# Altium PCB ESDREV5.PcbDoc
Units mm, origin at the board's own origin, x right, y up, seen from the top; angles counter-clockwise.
Board outline 53.34 x 50.29 mm, 2 copper layers (TopLayer, BottomLayer); 24 components, 34 nets, 104 pads, 29 vias.
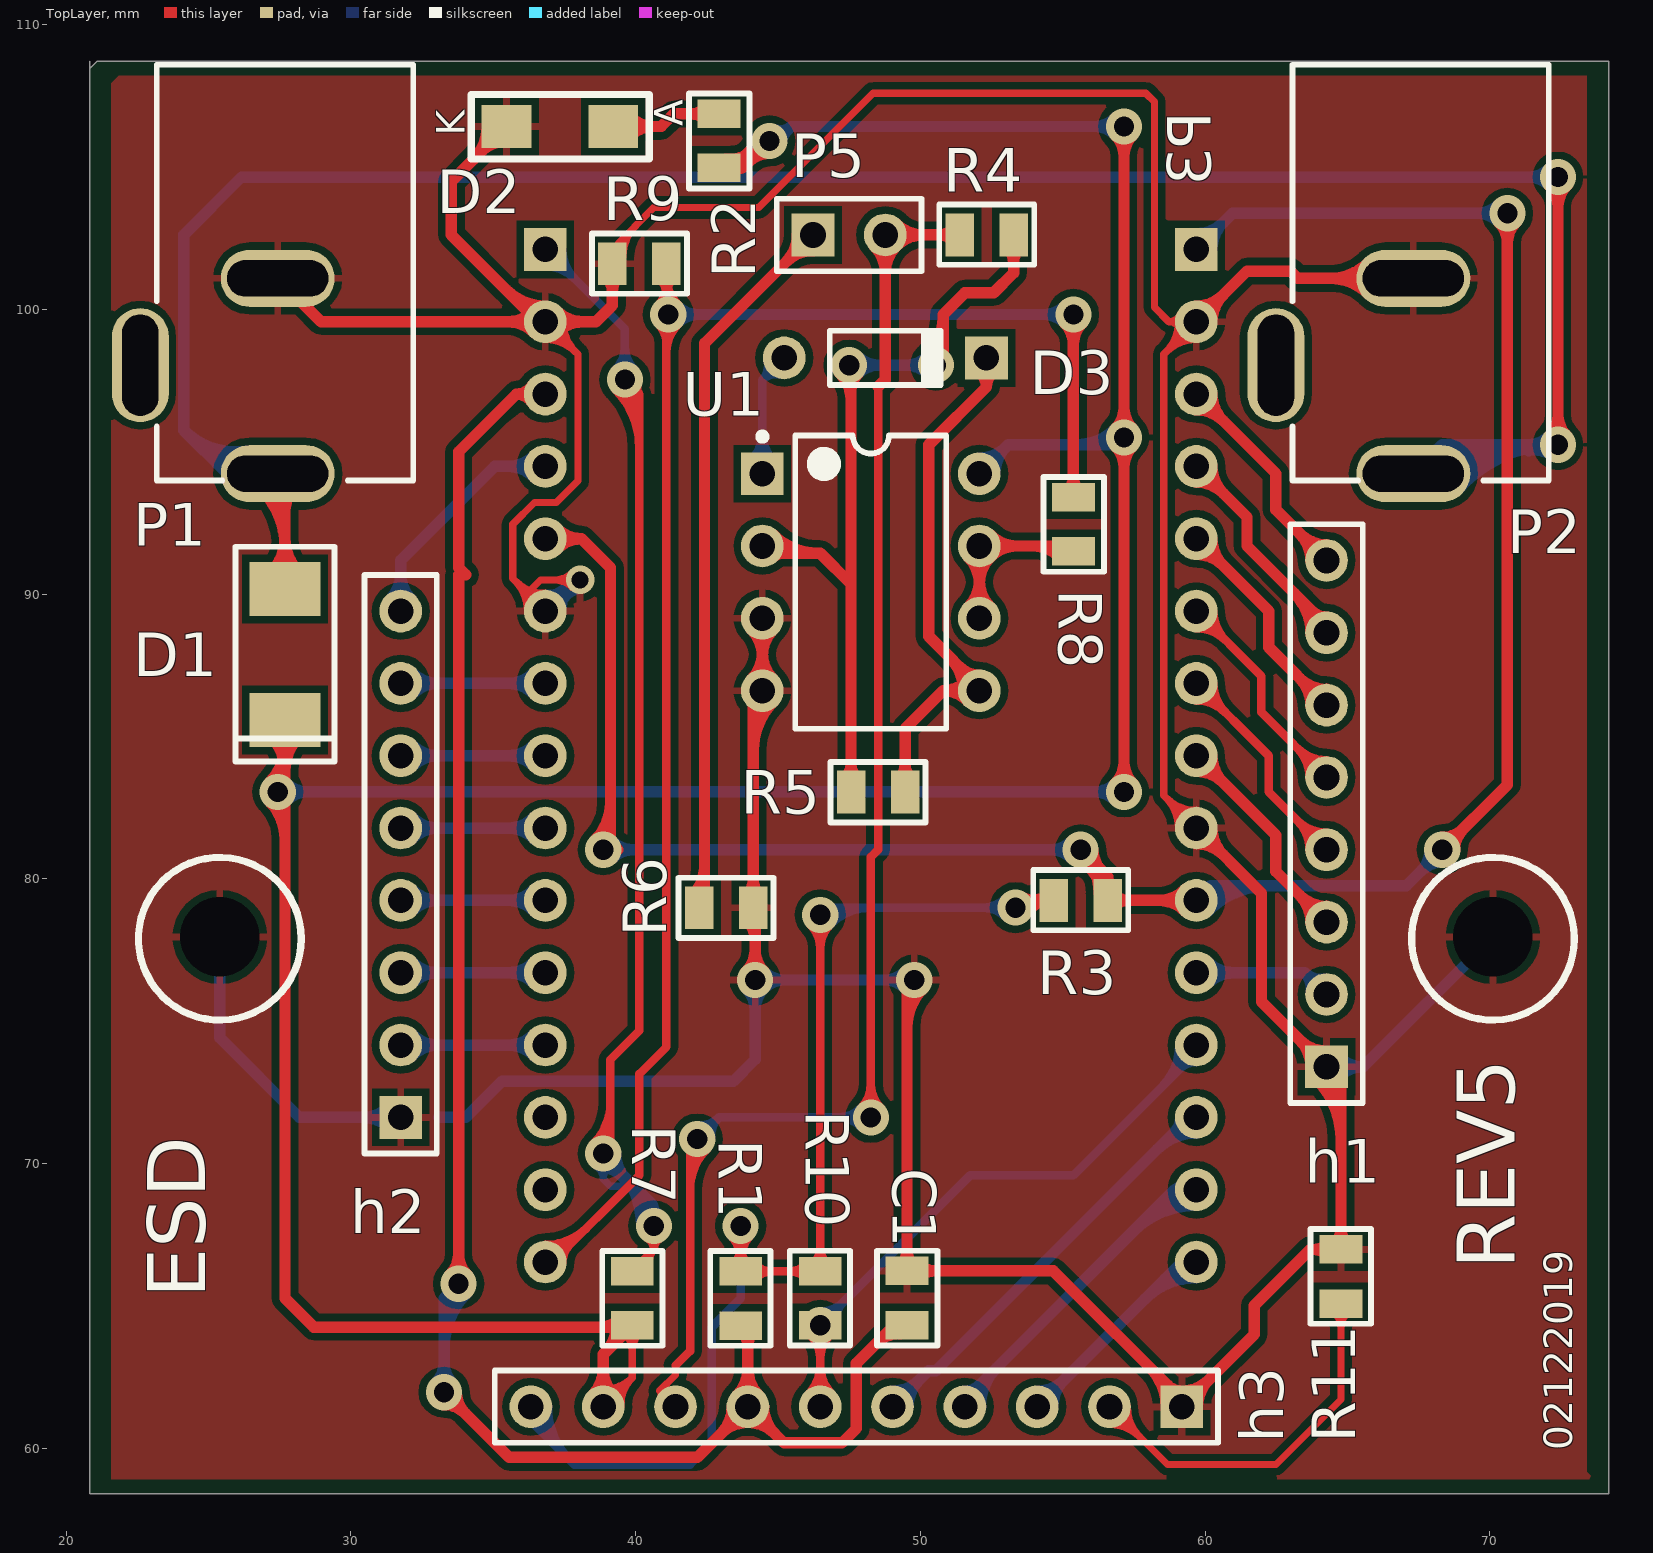
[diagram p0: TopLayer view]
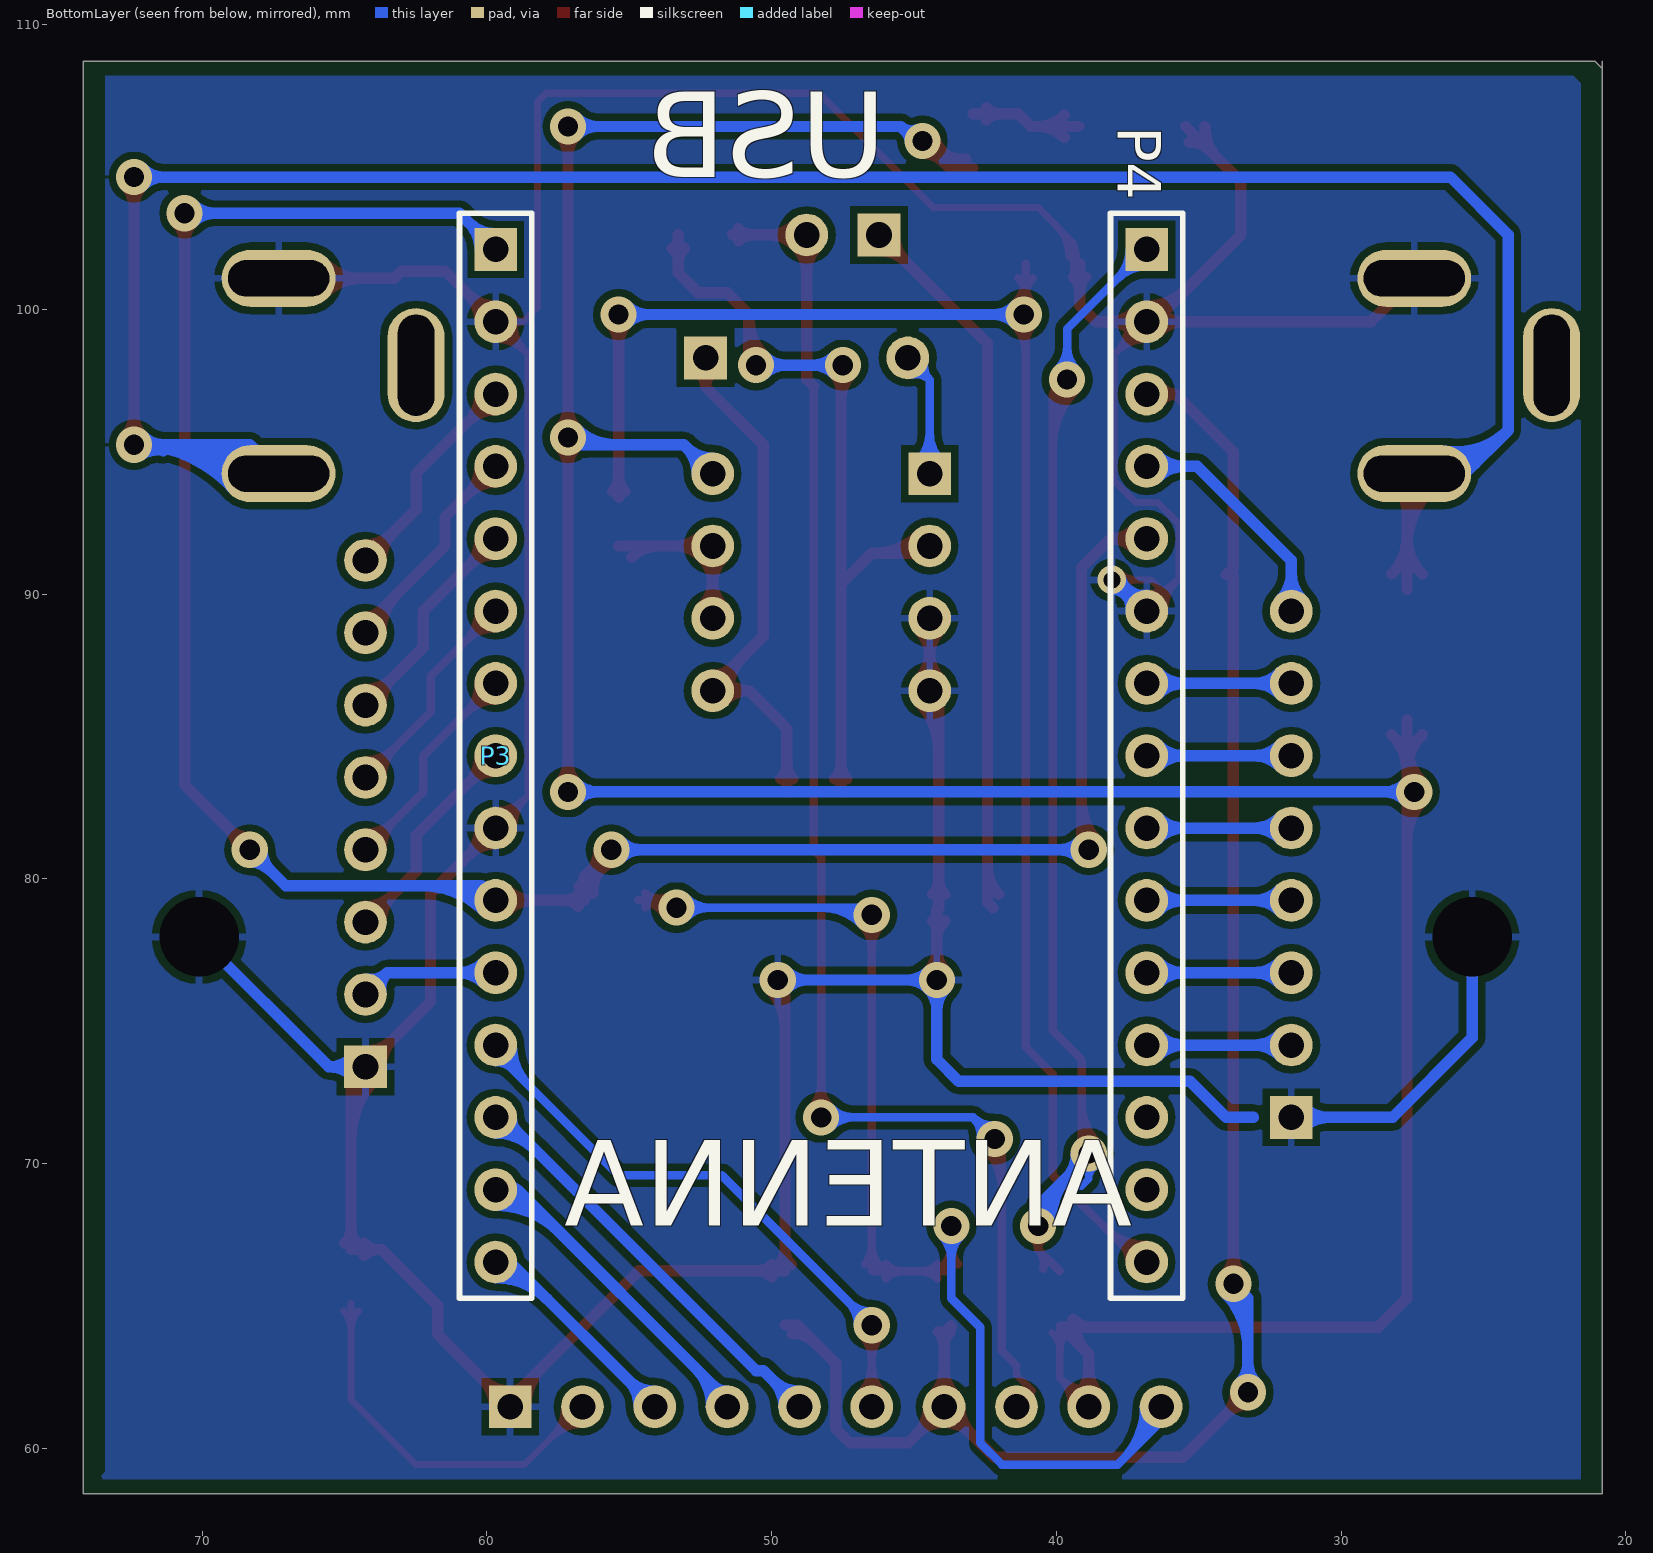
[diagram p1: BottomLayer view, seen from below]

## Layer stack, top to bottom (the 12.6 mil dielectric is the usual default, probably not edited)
TopLayer: signal copper 0.0356
Dielectric: core 0.32, FR-4, Dk 4.8
BottomLayer: signal copper 0.0356

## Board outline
20.828,108.458 21.082,108.712 74.168,108.712 74.168,58.42 20.828,58.42 20.828,108.712

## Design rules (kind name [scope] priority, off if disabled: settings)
AssemblyTestPointUsage AssemblyTestPointUsage_1 [All] p2:
AssemblyTestpoint AssemblyTestpoint_1 [All] p2: testpointundercomponent=TRUE minsize=1.016 maxsize=2.54 preferedsize=1.524 minholesize=0 maxholesize=1.016 preferedholesize=0.813 testpointgrid=0.025 usegrid=TRUE gridtolerance=0 allowsidetop=TRUE allowsidebottom=TRUE
Clearance [All] p1: gap=0.254
ComponentClearance ComponentClearance_1 [All] p2: gap=0.254 collisioncheckmode=3 verticalgap=0.254 showdistances=FALSE
DiffPairsRouting DiffPairsRouting_1 [All] p2: maxlimit=0.254 minlimit=0.254 mostfreqgap=0.254 maxuncoupledlength=12.7
FabricationTestPointUsage TestPointUsage [All] p2: valid=0 allowmultiple=FALSE
FabricationTestpoint Testpoint [All] p2: side=3 testpointundercomponent=TRUE minsize=1.016 maxsize=2.54 preferedsize=1.524 minholesize=0.508 maxholesize=1.016 preferedholesize=0.813 testpointgrid=0.025 allowsidetop=TRUE allowsidebottom=TRUE usegrid=TRUE gridtolerance=0
FanoutControl Fanout_LCC [IsLCC] p1: bgadir=Out bgaviamode=Centered fanoutstyle=Auto fanoutdirection=Alternating viagrid=0.025 // Fanout_LCC (Default Rule)
FanoutControl Fanout_BGA [IsBGA] p2: bgadir=Out bgaviamode=Centered fanoutstyle=Auto fanoutdirection=Alternating viagrid=0.025 // Fanout_BGA (Default Rule)
FanoutControl Fanout_Small [(CompPinCount < 5)] p3: bgadir=Out bgaviamode=Centered fanoutstyle=Auto fanoutdirection=OutThenIn viagrid=0.025 // Fanout_Small (Default Rule)
FanoutControl Fanout_SOIC [IsSOIC] p4: bgadir=Out bgaviamode=Centered fanoutstyle=Auto fanoutdirection=Alternating viagrid=0.025 // Fanout_SOIC (Default Rule)
FanoutControl Fanout_BGA_1 [IsBGA] p6: bgadir=Out bgaviamode=Centered fanoutstyle=Auto fanoutdirection=Alternating viagrid=0.025 // Fanout_BGA (Default Rule)
FanoutControl Fanout_LCC_1 [IsLCC] p7: bgadir=Out bgaviamode=Centered fanoutstyle=Auto fanoutdirection=Alternating viagrid=0.025 // Fanout_LCC (Default Rule)
FanoutControl Fanout_SOIC_1 [IsSOIC] p8: bgadir=Out bgaviamode=Centered fanoutstyle=Auto fanoutdirection=Alternating viagrid=0.025 // Fanout_SOIC (Default Rule)
FanoutControl Fanout_Small_1 [(CompPinCount < 5)] p9: bgadir=Out bgaviamode=Centered fanoutstyle=Auto fanoutdirection=OutThenIn viagrid=0.025 // Fanout_Small (Default Rule)
FanoutControl Fanout_Default_1 [All] p10: bgadir=Out bgaviamode=Centered fanoutstyle=Auto fanoutdirection=Alternating viagrid=0.025 // Fanout_Default (Default Rule)
Height Height_1 [All] p2: minheight=0 maxheight=25.4 prefheight=12.7
HoleSize HoleSize_1 [All] p2: absolutevalues=TRUE maxlimit=2.54 minlimit=0.025 maxpercent=80.000 minpercent=20.000
HoleToHoleClearance HoleToHoleClearance_1 [All] p2: gap=0.254 allowstackedmicrovias=TRUE
LayerPairs LayerPairs_1 [All] p2: enforce=TRUE
MinimumSolderMaskSliver MinimumSolderMaskSliver_1 [All] p2: minsoldermaskwidth=0.254
NetAntennae NetAntennae_1 [All] p2: netantennaetolerance=0
PasteMaskExpansion PasteMaskExpansion_1 [All] p2: expansion=0
PlaneClearance PlaneClearance_1 [All] p2: clearance=0.254
PolygonConnect [All] p1: connectstyle=Relief reliefconductorwidth=0.254 reliefentries=4 polygonreliefangle="90 Angle" airgapwidth=0.254
PolygonConnect PolygonConnect_1 [All] p2: connectstyle=Relief reliefconductorwidth=0.254 reliefentries=4 polygonreliefangle="90 Angle" airgapwidth=0.254
RoutingPriority RoutingPriority_1 [All] p2: routingpriority=0
RoutingTopology RoutingTopology_1 [All] p2: topology=Shortest
RoutingVias [All] p1: holewidth=0.6 width=1 viastyle="Through Hole" minholewidth=0.711 minwidth=1.27 maxholewidth=0.711 maxwidth=1.27
ShortCircuit ShortCircuit_1 [All] p2: allowed=FALSE
SilkToSilkClearance SilkToSilkClearance_1 [All] p2: silktosilkclearance=0.254
SilkToSolderMaskClearance SilkscreenOverComponentPads [IsPad] p2: minsilkscreentomaskgap=0.254 clearancetoexposedcopper=TRUE
SolderMaskExpansion [All] p1: expansion=0.102
SolderMaskExpansion SolderMaskExpansion_1 [All] p2: expansion=0.051
UnRoutedNet UnRoutedNet_1 [All] p2:
Width [All] p1: maxlimit=0.5 minlimit=0.254 preferedwidth=0.254
24 further rules are at their usual default settings.

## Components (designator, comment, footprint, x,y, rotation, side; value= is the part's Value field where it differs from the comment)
C1 "100nF" 0805#1 49.53,65.278 r270 top
D1 "1.5A, PIV 1KV" DO-214AA 27.686,87.884 r90 top
D2 "LED3" "0537, LED, 1206" 37.338,106.426 r0 top
D3 "Diode 1N4448" DO-35 48.768,98.298 r0 top
h1 "Header 8" HDR1X8 64.262,73.406 r90 top
h2 "Header 8" HDR1X8 31.75,71.628 r90 top
h3 "Header 10" HDR1X10 59.182,61.468 r180 top
P1 "Header 2" DCJACK 27.432,101.092 r270 top
P2 "Header 2" DCJACK 67.31,101.092 r270 top
P3 "Header 15" HDR1X15 59.69,102.108 r270 bottom
P4 "Header 15" HDR1X15 36.83,102.108 r270 bottom
P5 "Header 2" HDR1X2 46.228,102.616 r0 top
R1 "" 0805#1 43.688,65.278 r90 top
R2 "R" 0805#2 42.926,105.918 r270 top
R3 "" 0805#2 55.626,79.248 r0 top
R4 "R" 0805#2 52.324,102.616 r0 top
R5 "R" 0805#2 48.514,83.058 r180 top
R6 "" 0805#2 43.18,78.994 r180 top
R7 "" 0805#2 39.878,65.278 r270 top
R8 "" 0805#2 55.372,92.456 r270 top
R9 "" 0805#2 40.132,101.6 r0 top
R10 "" 0805#2 46.482,65.278 r90 top
R11 "" 0805#2 64.77,66.04 r90 top
U1 "LT1079" DIP-8 48.26,90.424 r0 top

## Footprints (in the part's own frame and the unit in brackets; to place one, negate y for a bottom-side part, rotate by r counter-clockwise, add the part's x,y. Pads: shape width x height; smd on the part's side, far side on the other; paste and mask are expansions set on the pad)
"0537, LED, 1206" [mm]
  rect 1.75x1.5 smd: A(1.875,0) K(-1.875,0)
  silkscreen extent -3.11,-1.14 3.14,1.12, body extent -1.6,-0.8 1.6,0.8, height 1.52
0805#1 [mm]
  rect 1x1.5 smd: 1(-0.959,-0.002) 2(0.941,-0.002)
  silkscreen extent -1.67,-1.05 1.66,1.07
0805#2 [mm]
  rect 1x1.5 smd: 1(-0.95,0) 2(0.95,0)
  silkscreen extent -1.66,-1.05 1.67,1.07, body extent -1.1,-0.72 1.14,0.73, height 0.75
DCJACK [mm]
  oval 2x4 hole 1.27 slot 3.556 at 90 deg: 1(6.858,0) 2(0,0)
  oval 4x2 hole 1.27 slot 3.556 at 0 deg: 3(3.048,-4.826)
  silkscreen extent -7.5,-4.25 7.1,4.75
DIP-8 [mm] "DIP; 8 Leads; Row Spacing 7.62 mm; Pitch 2.54 mm"
  rect 1.5x1.5 hole 0.9: 1(-3.81,3.81)
  round 1.5 hole 0.9: 2(-3.81,1.27) 3(-3.81,-1.27) 4(-3.81,-3.81) 5(3.81,-3.81) 6(3.81,-1.27) 7(3.81,1.27) 8(3.81,3.81)
  silkscreen extent -3.93,-5.15 2.65,5.23, body extent -3.6,-5.15 3.6,5.15, height 5.08
DO-35 [mm] "Diode, Axial; Body 3.8 x 1.9 mm (LxDia. max), Lead Dia. 0.53 mm (max)"
  round 1.5 hole 0.9: 1(-3.55,0)
  rect 1.5x1.5 hole 0.9: 2(3.55,0)
  silkscreen extent -1.95,-0.95 2.05,0.95
DO-214AA [mm]
  rect 1.9x2.5 smd: A(2.295,0) K(-2.295,0)
  silkscreen extent -3.75,-1.74 3.79,1.74, body extent -2.72,-1.98 2.88,1.96, height 2.3
HDR1X2 [mm] "Connector; Header; 2 Position"
  rect 1.5x1.5 hole 0.9: 1(0,0)
  round 1.5 hole 0.9: 2(2.54,0)
  silkscreen extent -1.27,-1.27 3.81,1.27
HDR1X8 [mm] "Connector; Header; 8 Position"
  rect 1.5x1.5 hole 0.9: 1(0,0)
  round 1.5 hole 0.9: 2(2.54,0) 3(5.08,0) 4(7.62,0) 5(10.16,0) 6(12.7,0) 7(15.24,0) 8(17.78,0)
  silkscreen extent -1.27,-1.27 19.05,1.27
HDR1X10 [mm] "Connector; Header; 10 Position"
  rect 1.5x1.5 hole 0.9: 1(0,0)
  round 1.5 hole 0.9: 2(2.54,0) 3(5.08,0) 4(7.62,0) 5(10.16,0) 6(12.7,0) 7(15.24,0) 8(17.78,0) 9(20.32,0) 10(22.86,0)
  silkscreen extent -1.27,-1.27 24.13,1.27
HDR1X15 [mm] "Connector; Header; 15 Position"
  rect 1.5x1.5 hole 0.9: 1(0,0)
  round 1.5 hole 0.9: 2(2.54,0) 3(5.08,0) 4(7.62,0) 5(10.16,0) 6(12.7,0) 7(15.24,0) 8(17.78,0) 9(20.32,0) 10(22.86,0) 11(25.4,0) 12(27.94,0) 13(30.48,0) 14(33.02,0) 15(35.56,0)
  silkscreen extent -1.27,-1.27 36.83,1.27

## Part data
C1: "Capacitor ceramic, SMD 0603, 10 UF, +/-10%, 16 V dc"
D1: "Diode high voltage, SMD DO-214AA, If 1.5 A, PIV 1 kV"
D2: "Typical BLUE SiC LED"
D3: "High Conductance Fast Diode"
h1 h2: "Header, 8-Pin"
h3: "Header, 10-Pin"
P1 P2 P5: "Header, 2-Pin"
P3 P4: "Header, 15-Pin"
R1 R2 R6: library part BRS133-473, "Resistor SMD 0603, 4.7 k Ohm, +/-5%, 1/10W"
R3 R8: library part BRS133-473, "Resistor SMD 0805, 1.5 k Ohm, +/-1%, 1/8W"
R4 R5: library part BRS133-473, "Resistor SMD 0805, 220 k Ohm, +/-1%, 1/8W"
R7: library part BRS133-473, "Resistor SMD 0603, 0 Ohm, +/-5%, 1/10W"
R9: library part BRS133-473, "Resistor SMD 1206, 10 k Ohm, +/-5%, 1/4W"
R10 R11: library part BRS133-473, "Resistor SMD 0603, 470 Ohm, +/-5%, 1/10W"

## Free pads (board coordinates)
  round 1.27 hole 2.794: 1(25.4,77.965) 2(70.104,77.965)

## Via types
v1: diameter 1.27, hole 0.711, TopLayer to BottomLayer, 28 vias
v2: diameter 1, hole 0.6, TopLayer to BottomLayer, 1 vias

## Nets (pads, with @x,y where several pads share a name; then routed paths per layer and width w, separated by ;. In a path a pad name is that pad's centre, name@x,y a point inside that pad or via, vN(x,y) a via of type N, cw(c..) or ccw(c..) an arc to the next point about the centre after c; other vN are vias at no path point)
3V3: P3.1 P3.10 P4.5 R3.2 | length 120.1
  TopLayer w0.254: v1@55.713,80.526 cw(c55.79,80.085) 56.199,80.266 ; v1@55.723,80.527 cw(c55.805,80.106) 56.198,80.279 ; v1@56.046,80.913 56.103,80.549 56.173,80.1 ; 56.117,80.463 ccw(c57.43,80.668) R3.2@56.646,79.594 ; 56.119,80.446 ccw(c57.392,80.645) R3.2@56.645,79.595 ; 56.14,80.312 ccw(c55.178,80.161) v1(55.626,81.026) cw(c54.825,79.929) 56.167,80.139 ; 56.242,80.168 ccw(c55.219,79.715) 55.551,80.783 cw(c55.216,79.704) 56.25,80.161 ; v1@56.1,80.843 ccw(c56.541,80.672) 56.109,80.481 cw(c56.541,80.672) v1@56.1,80.843 ; v1@56.1,80.843 ccw(c56.555,80.667) 56.109,80.469 cw(c56.555,80.667) v1@56.1,80.843
  TopLayer w0.4: P4.5 38.1,91.948 ; P4.5@37.231,91.572 cw(c38.1,90.757) 38.1,91.948 ; P4.5@37.231,92.324 ccw(c38.1,93.139) 38.1,91.948 ; v1@38.554,81.334 ccw(c37.199,82.689) 39.116,82.689 ; v1@38.837,81.051 ccw(c38.164,81.724) 39.116,81.724 ; v1(38.862,81.026) 39.37,81.026 39.116,81.28 39.116,90.932 38.1,91.948 ; v1@55.513,80.606 cw(c55.232,79.556) 56.173,80.1 ; v1@55.626,80.591 cw(c55.626,79.541) 56.369,80.283 cw(c57.111,81.026) v1@56.061,81.026 ; v1(55.626,81.026) 56.576,80.076 ; v1@55.655,80.997 cw(c54.156,79.498) R3.2@56.276,79.498 ; v1@56.046,80.913 ccw(c57.025,80.651) 56.147,80.144 ; 56.338,80.314 cw(c55.522,79.498) R3.2@56.676,79.498 ; R3.2@56.403,79.743 ccw(c56.169,80.076) 56.576,80.076 ; R3.2@56.749,79.743 cw(c56.983,80.076) 56.576,80.076 ; R3.2@56.788,79.036 cw(c57.3,78.524) 57.3,79.248 cw(c57.3,79.972) R3.2@56.788,79.46 ; P3.10@59.301,78.859 ccw(c58.362,77.92) 58.362,79.248 ccw(c58.362,80.576) P3.10@59.301,79.637 ; P3.10 R3.2 56.576,80.076 ; v1(68.326,81.026) 70.612,83.312 v1(70.612,103.378) ; v1@68.326,81.461 ccw(c68.326,82.511) 69.069,81.769 ccw(c69.811,81.026) v1@68.761,81.026 ; v1@70.304,103.07 cw(c69.562,102.328) 70.612,102.328 cw(c71.662,102.328) v1@70.92,103.07
  BottomLayer w0.4: v1(38.862,81.026) v1(55.626,81.026) v1@55.88,81.026 ; v1@39.17,80.718 cw(c39.912,79.976) 39.912,81.026 cw(c39.912,82.076) v1@39.17,81.334 ; v1@55.318,80.718 ccw(c54.576,79.976) 54.576,81.026 ccw(c54.576,82.076) v1@55.318,81.334 ; P3.10@59.513,79.425 cw(c60.313,78.625) 60.313,79.756 ; P3.10 60.198,79.756 67.056,79.756 v1(68.326,81.026) ; P3.1 60.96,103.378 v1(70.612,103.378) ; P3.1@59.69,102.658 ccw(c59.69,103.986) 60.629,103.047 ccw(c61.568,102.108) P3.1@60.24,102.108 ; P3.10@59.796,79.142 cw(c61.279,77.659) 61.279,79.756 ; P3.10@60.079,78.859 cw(c62.244,76.694) 62.244,79.756 ; v1@67.891,81.026 cw(c66.841,81.026) 67.583,80.283 cw(c68.326,79.541) v1@68.326,80.591 ; v1@70.304,103.07 ccw(c69.562,102.328) 69.562,103.378 ccw(c69.562,104.428) v1@70.304,103.686
5VIN: D1.A P1.1 P2.1 | length 112.9
  TopLayer w0.4: P1.1@26.866,93.668 cw(c24.887,91.689) 27.686,91.689 ; P1.1@27.149,93.951 cw(c25.853,92.655) 27.686,92.655 ; D1.A@27.156,90.709 ccw(c25.875,91.99) 27.686,91.99 ccw(c29.497,91.99) D1.A@28.216,90.709 ; P1.1 27.686,93.98 D1.A ; 27.686,92.916 cw(c28.75,92.916) P1.1@27.998,93.668 ; v1@72.082,95.558 ccw(c71.34,96.3) 72.39,96.3 ccw(c73.44,96.3) v1@72.698,95.558 ; v1@72.082,104.34 cw(c71.34,103.598) 72.39,103.598 cw(c73.44,103.598) v1@72.698,104.34 ; v1(72.39,95.25) v1(72.39,104.648)
  BottomLayer w0.4: 24.697,95.191 ccw(c26.099,96.593) P1.1@26.376,94.63 ; 25.264,94.624 ccw(c26.239,95.6) P1.1@26.432,94.234 ; P1.1@26.32,95.026 cw(c25.958,97.586) 24.13,95.758 ; P1.1 25.654,94.234 24.13,95.758 ; P2.1 68.326,95.25 v1(72.39,95.25) ccw(c72.39,90.559) P2.1@68.904,93.699 ; P2.1@67.716,94.769 cw(c68.795,93.797) 68.795,95.25 ; P2.1@68.013,94.502 cw(c69.694,92.988) 69.694,95.25 ; P2.1@68.31,94.234 cw(c70.593,92.178) 70.593,95.25 ; P2.1@68.607,93.966 cw(c71.491,91.369) 71.491,95.25 ; v1@72.028,95.491 cw(c71.155,96.074) 71.36,95.045 cw(c71.566,94.014) v1@72.149,94.888 ; v1@72.082,94.942 ccw(c71.34,94.2) 71.34,95.25 ccw(c71.34,96.3) v1@72.082,95.558 ; v1@72.082,104.34 ccw(c71.34,103.598) 71.34,104.648 ccw(c71.34,105.698) v1@72.082,104.956 ; v1(72.39,104.648) 26.162,104.648 24.13,102.616 24.13,95.758
+5: D1.K h3.9 R2.2 R7.2 U1.8 | length 152.9
  TopLayer w0.254: h3.9 39.878,62.484 ; h3.9@38.874,61.837 ccw(c38.9,62.633) 39.464,62.07 ccw(c40.027,61.506) h3.9@39.231,61.48 ; h3.9@38.882,62.091 ccw(c38.927,63.435) 39.878,62.484 ; h3.9@39.485,61.488 cw(c40.829,61.533) 39.878,62.484 ; R7.2@39.614,64.064 cw(c38.978,63.427) 39.878,63.427 cw(c40.778,63.427) R7.2@40.142,64.064 ; R7.2 39.878,62.484
  TopLayer w0.4: v1@27.124,82.75 cw(c25.769,81.395) 27.686,81.395 ; v1@27.124,83.366 ccw(c25.769,84.721) D1.K@27.686,84.721 ; D1.K@27.156,85.059 cw(c25.875,83.778) 27.686,83.778 cw(c29.497,83.778) D1.K@28.216,85.059 ; v1@27.407,83.033 cw(c26.734,82.36) 27.686,82.36 ; v1@27.407,83.083 ccw(c26.734,83.756) 27.686,83.756 ; D1.K 27.686,65.278 28.702,64.262 39.812,64.262 38.862,63.312 h3.9 ; h3.9@38.473,61.857 ccw(c37.534,62.796) 38.862,62.796 ccw(c40.19,62.796) h3.9@39.251,61.857 ; 38.744,64.262 ccw(c38.744,65.212) R7.2@39.416,64.54 ; 38.939,63.389 ccw(c38,64.328) R7.2@39.328,64.328 ; 39.063,64.262 cw(c39.063,63.763) R7.2@39.416,64.116 ; R2.2 43.754,104.968 ; R2.2@43.176,104.868 ccw(c43.176,106.022) 43.992,105.206 ; R2.2@43.176,105.268 ccw(c43.176,107.388) v1@44.675,105.889 ; R2.2@43.421,104.795 cw(c43.754,104.561) 43.754,104.968 ; R2.2@43.421,105.141 ccw(c43.754,105.375) 43.754,104.968 ; 43.778,105.371 ccw(c43.234,106.312) v1@44.284,106.031 ; 43.822,105.397 cw(c44.329,104.519) v1@44.591,105.498 ; v1@44.269,105.918 cw(c43.219,105.918) 43.961,105.175 cw(c44.704,104.433) v1@44.704,105.483 ; v1(44.704,105.918) 43.754,104.968 ; v1@56.842,83.366 ccw(c56.1,84.108) 57.15,84.108 ccw(c58.2,84.108) v1@57.458,83.366 ; v1@56.842,95.196 cw(c56.1,94.454) 57.15,94.454 cw(c58.2,94.454) v1@57.458,95.196 ; v1@56.842,95.812 ccw(c56.1,96.554) 57.15,96.554 ccw(c58.2,96.554) v1@57.458,95.812 ; v1@56.842,106.118 cw(c56.1,105.376) 57.15,105.376 cw(c58.2,105.376) v1@57.458,106.118 ; v1(57.15,83.058) v1(57.15,95.504) v1(57.15,106.426)
  BottomLayer w0.4: v1(27.432,83.058) v1(57.15,83.058) ; v1@27.74,82.75 cw(c28.482,82.008) 28.482,83.058 cw(c28.482,84.108) v1@27.74,83.366 ; v1(44.704,105.918) 44.958,105.918 45.466,106.426 ; v1@44.879,106.316 ccw(c45.092,106.8) 45.466,106.426 ; v1@45.139,105.918 cw(c45.576,105.918) 45.267,106.227 ; U1.8 53.086,95.25 56.896,95.25 v1(57.15,95.504) ; U1.8@52.07,94.784 ccw(c52.07,96.112) 53.009,95.173 ccw(c53.948,94.234) U1.8@52.62,94.234 ; 55.487,95.25 ccw(c55.487,97.167) v1@56.842,95.812 ; 56.452,95.25 ccw(c56.452,96.202) v1@57.125,95.529 ; v1@56.842,82.75 ccw(c56.1,82.008) 56.1,83.058 ccw(c56.1,84.108) v1@56.842,83.366 ; v1@56.842,106.118 ccw(c56.1,105.376) 56.1,106.426 ccw(c56.1,107.476) v1@56.842,106.734 ; v1(57.15,106.426) 45.466,106.426
+VCC3_5: h3.10 R1.2 R3.1 R10.2 | length 66.5
  TopLayer w0.3: v1@43.345,67.475 cw(c42.512,66.642) R1.2@43.69,66.642 ; R1.2@43.443,66.466 ccw(c42.845,67.064) 43.69,67.064 ccw(c44.535,67.064) R1.2@43.938,66.466 ; v1(43.688,67.818) 43.69,67.816 R1.2 46.473,66.219 R10.2 46.482,77.978 ; R1.2@43.69,66.652 cw(c44.854,66.652) v1@44.031,67.475 ; R1.2@44.188,65.971 cw(c44.785,65.374) 44.785,66.219 cw(c44.785,67.064) R1.2@44.188,66.466 ; 45.364,66.219 ccw(c45.364,67.096) R10.2@45.985,66.475 ; 45.41,66.219 cw(c45.41,65.406) R10.2@45.985,65.981 ; v1@46.139,78.397 cw(c45.311,77.569) 46.482,77.569 cw(c47.653,77.569) v1@46.825,78.397 ; R10.2@46.235,66.475 ccw(c45.637,67.073) 46.482,67.073 ccw(c47.327,67.073) R10.2@46.729,66.475 ; v1(46.482,78.74) 46.482,77.978 ; v1(53.34,78.994) 53.594,79.248 R3.1 ccw(c54.676,78.156) v1@53.751,78.736 ; v1@53.497,78.896 cw(c54.134,78.496) 54.134,79.248 ; v1@53.582,79.414 ccw(c53.966,80.078) 54.165,79.337 ; R3.1@54.429,79.001 ccw(c53.831,78.403) 53.831,79.248 ccw(c53.831,80.093) R3.1@54.429,79.495 ; 46.482,77.978 cw(c46.838,77.978) 46.687,78.301 ccw(c46.838,77.978) 46.482,77.978 ; 46.482,77.978 ccw(c46.126,77.978) 46.277,78.301 cw(c46.126,77.978) 46.482,77.978
  BottomLayer w0.3: h3.10@36.622,61.468 ccw(c38.573,61.468) 37.193,60.089 ; 36.681,60.601 cw(c37.548,61.468) h3.10 36.322,60.96 37.846,59.436 41.91,59.436 42.672,60.198 42.672,64.262 43.688,65.278 v1(43.688,67.818) ; h3.10@36.922,61.468 ccw(c39.597,61.468) 37.705,59.577 ; v1@43.345,67.475 cw(c42.517,66.647) 43.688,66.647 cw(c44.859,66.647) v1@44.031,67.475 ; v1(46.482,78.74) 46.736,78.994 v1(53.34,78.994) ; v1@46.613,78.609 cw(c47.542,77.68) 47.542,78.994 ; v1@46.825,78.397 cw(c48.266,76.956) 48.266,78.994 ; v1@52.997,78.651 ccw(c52.169,77.823) 52.169,78.994 ccw(c52.169,80.165) v1@52.997,79.337
ADC0: P4.15 R8.1 R9.2 | length 72
  TopLayer w0.3: P4.15 37.084,66.548 40.132,69.596 40.132,73.152 41.082,74.102 R9.2 ; P4.15@36.83,66.848 ccw(c36.83,68.185) 37.776,67.24 ; P4.15@36.83,67.148 ccw(c36.83,69.21) 38.288,67.752 ; P4.15@37.43,66.548 cw(c38.265,66.548) 37.675,67.139 ; v1@40.805,99.479 cw(c40.136,98.81) 41.082,98.81 ; v1@40.805,100.165 ccw(c40.136,100.834) 41.082,100.834 ; R9.2@40.835,101.103 cw(c40.237,100.505) 41.082,100.505 cw(c41.927,100.505) R9.2@41.329,101.103 ; 41.082,98.492 cw(c42.478,98.492) v1@41.491,99.479 ; R9.2@41.082,101.152 ccw(c42.478,101.152) v1@41.491,100.165
  TopLayer w0.4: v1@55.064,99.514 cw(c54.322,98.772) 55.372,98.772 cw(c56.422,98.772) v1@55.68,99.514 ; R8.1@55.16,93.618 ccw(c54.648,94.13) 55.372,94.13 ccw(c56.096,94.13) R8.1@55.584,93.618 ; R8.1 v1(55.372,99.822)
  BottomLayer w0.4: v1(41.148,99.822) v1(55.372,99.822) ; v1@41.456,99.514 cw(c42.198,98.772) 42.198,99.822 cw(c42.198,100.872) v1@41.456,100.13 ; v1@55.064,99.514 ccw(c54.322,98.772) 54.322,99.822 ccw(c54.322,100.872) v1@55.064,100.13
CHD: h2.5 P4.9 | length 9.3
  BottomLayer w0.4: h2.5 P4.9 ; h2.5@32.139,81.399 cw(c33.078,80.46) 33.078,81.788 cw(c33.078,83.116) h2.5@32.139,82.177 ; P4.9@36.441,81.399 ccw(c35.502,80.46) 35.502,81.788 ccw(c35.502,83.116) P4.9@36.441,82.177
CLK: h2.7 P4.7 | length 9.3
  BottomLayer w0.4: h2.7 P4.7 ; h2.7@32.139,86.479 cw(c33.078,85.54) 33.078,86.868 cw(c33.078,88.196) h2.7@32.139,87.257 ; P4.7@36.441,86.479 ccw(c35.502,85.54) 35.502,86.868 ccw(c35.502,88.196) P4.7@36.441,87.257
D0: h3.3 P3.15 | length 13
  BottomLayer w0.4: h3.3 59.182,66.548 P3.15 ; h3.3@54.102,62.018 ccw(c54.102,63.346) 55.041,62.407 ccw(c55.98,61.468) h3.3@54.652,61.468 ; 57.884,65.25 cw(c59.69,63.444) P3.15@59.69,65.998 ; 58.567,65.933 cw(c59.69,64.809) P3.15@59.69,66.398
D1: h3.4 P3.14 | length 20.1
  BottomLayer w0.4: h3.4 51.562,61.722 58.928,69.088 ; h3.4@51.562,62.018 ccw(c51.562,62.733) 52.067,62.227 ; h3.4@51.712,61.468 cw(c52.687,61.468) 51.998,62.158 ; h3.4@52.112,61.468 cw(c54.053,61.468) 52.681,62.841 ; 57.45,67.61 cw(c59.69,65.371) P3.14@59.69,68.538 ; 58.133,68.293 cw(c59.69,66.736) P3.14@59.69,68.938 ; 58.816,68.976 cw(c59.69,68.102) P3.14@59.69,69.338 ; P3.14@59.168,68.915 ccw(c58.928,68.835) 58.928,69.088 ; P3.14@59.168,69.261 cw(c58.928,69.341) 58.928,69.088 ; P3.14 58.928,69.088
D2: h3.5 P3.13 | length 19.8
  BottomLayer w0.4: h3.5 50.292,62.738 50.546,62.738 59.436,71.628 P3.13 ; h3.5@49.022,62.018 ccw(c49.022,63.346) 49.961,62.407 ccw(c50.9,61.468) h3.5@49.572,61.468 ; 58.317,70.509 cw(c59.69,69.137) P3.13@59.69,71.078 ; 58.931,71.123 ccw(c58.425,71.628) P3.13@59.14,71.628 ; 59,71.192 cw(c59.69,70.503) P3.13@59.69,71.478
D3: h3.6 P3.12 R10.1 | length 30.9
  TopLayer w0.3: h3.6@46.058,61.892 ccw(c45.033,62.917) 46.482,62.917 ccw(c47.931,62.917) h3.6@46.906,61.892 ; R10.1@46.139,63.985 cw(c45.311,63.157) 46.482,63.157 cw(c47.653,63.157) R10.1@46.825,63.985 ; R10.1@46.235,64.081 cw(c45.637,63.483) 46.482,63.483 cw(c47.327,63.483) R10.1@46.729,64.081 ; h3.6 v1(46.482,64.328)
  BottomLayer w0.3: v1(46.482,64.328) 51.75,69.596 55.372,69.596 59.69,73.914 P3.12 ; v1@46.482,64.813 ccw(c46.482,65.984) 47.31,65.156 ccw(c48.138,64.328) v1@46.967,64.328 ; 58.486,72.71 ccw(c57.028,74.168) P3.12@59.09,74.168 ; 58.998,73.222 ccw(c58.053,74.168) P3.12@59.39,74.168 ; 59.099,73.323 cw(c59.69,72.733) P3.12@59.69,73.568
D4: h1.2 P3.11 | length 8.4
  BottomLayer w0.4: P3.11 63.5,76.708 ; P3.11@60.079,76.319 cw(c61.018,75.38) 61.018,76.708 cw(c61.018,78.036) P3.11@60.079,77.097 ; h1.2@63.719,76.033 ccw(c62.948,76.156) 63.5,76.708 ; h1.2@64.175,76.489 cw(c64.052,77.26) 63.5,76.708 ; h1.2 63.5,76.708
D5: h1.3 P3.8 | length 11.9
  TopLayer w0.4: P3.8@59.69,83.778 cw(c59.69,82.45) 60.629,83.389 cw(c61.568,84.328) P3.8@60.24,84.328 ; P3.8 62.484,81.534 62.484,80.264 h1.3 ; h1.3@63.712,78.486 ccw(c62.384,78.486) 63.323,79.425 ccw(c64.262,80.364) h1.3@64.262,79.036
D6: h1.4 P3.7 | length 12.3
  TopLayer w0.3: P3.7@59.69,86.268 cw(c59.69,84.819) 60.714,85.844 cw(c61.739,86.868) P3.7@60.29,86.868 ; P3.7 62.23,84.328 62.23,83.058 h1.4 ; h1.4@63.662,81.026 ccw(c62.213,81.026) 63.238,82.05 ccw(c64.262,83.075) h1.4@64.262,81.626
D7: h1.5 P3.6 | length 12.3
  TopLayer w0.3: P3.6@59.69,88.808 cw(c59.69,87.359) 60.714,88.384 cw(c61.739,89.408) P3.6@60.29,89.408 ; P3.6 61.976,87.122 61.976,85.852 h1.5 ; h1.5@63.662,83.566 ccw(c62.213,83.566) 63.238,84.59 ccw(c64.262,85.615) h1.5@64.262,84.166
D8: h1.6 P3.5 | length 11.9
  TopLayer w0.4: P3.5@59.69,91.398 cw(c59.69,90.07) 60.629,91.009 cw(c61.568,91.948) P3.5@60.24,91.948 ; P3.5 62.23,89.408 62.23,88.138 h1.6 ; h1.6@63.712,86.106 ccw(c62.384,86.106) 63.323,87.045 ccw(c64.262,87.984) h1.6@64.262,86.656
EN: h2.8 P4.4 | length 12.4
  BottomLayer w0.4: h2.8@31.361,89.797 ccw(c30.422,90.736) 31.75,90.736 ccw(c33.078,90.736) h2.8@32.139,89.797 ; h2.8 31.75,91.186 35.052,94.488 P4.4 ; P4.4@36.441,94.099 ccw(c35.502,93.16) 35.502,94.488 ccw(c35.502,95.816) P4.4@36.441,94.877
ESDIN: h3.8 P5.2 R4.1 | length 64.1
  TopLayer w0.254: h3.8@40.871,61.794 ccw(c40.709,61.893) 40.843,62.027 ; h3.8@41.076,61.999 cw(c40.977,62.161) 40.843,62.027 ; h3.8 40.843,62.027 ; 41.402,62.917 41.402,62.586 40.843,62.027
  TopLayer w0.3: 41.402,62.917 41.91,63.425 41.91,70.612 v1(42.164,70.866) ; 41.91,69.082 cw(c43.948,69.082) v1@42.507,70.523 ; 41.91,69.806 cw(c43.224,69.806) v1@42.295,70.735 ; v1@47.917,71.971 ccw(c47.089,72.799) 48.26,72.799 ccw(c49.431,72.799) v1@48.603,71.971 ; v1(48.26,71.628) 48.26,80.772 48.514,81.026 48.514,97.282
  TopLayer w0.4: P5.2@48.379,102.227 cw(c47.44,101.288) 48.768,101.288 cw(c50.096,101.288) 49.157,102.227 cw(c50.096,101.288) 50.096,102.616 cw(c50.096,103.944) P5.2@49.157,103.005 ; 48.514,97.282 48.768,97.536 P5.2 R4.1 ; R4.1@51.162,102.404 ccw(c50.65,101.892) 50.65,102.616 ccw(c50.65,103.34) R4.1@51.162,102.828
  BottomLayer w0.3: v1(42.164,70.866) 42.926,71.628 ; v1@42.193,71.35 ccw(c42.251,72.303) 42.926,71.628 ; v1@42.648,70.895 cw(c43.601,70.953) 42.926,71.628 ; v1@47.917,71.285 ccw(c47.089,70.457) 47.089,71.628 ccw(c47.089,72.799) v1@47.917,71.971 ; v1(48.26,71.628) 42.926,71.628
ESDOUT1: R8.2 U1.6 U1.7 | length 13.2
  TopLayer w0.4: U1.6@51.681,89.543 ccw(c50.742,90.482) 52.07,90.482 ccw(c53.398,90.482) U1.6@52.459,89.543 ; U1.7@51.681,91.305 cw(c50.742,90.366) 52.07,90.366 cw(c53.398,90.366) 52.459,91.305 cw(c53.398,90.366) 53.398,91.694 cw(c53.398,93.022) U1.7@52.459,92.083 ; U1.6 U1.7 R8.2@55.372,91.694 ; 53.944,91.694 cw(c53.944,90.328) R8.2@54.91,91.294
GND: C1.1 D2.K h1.1 h2.1 h3.1 P1.2 P2.2 P3.2 P3.9 P4.2 P4.6 pad.1 pad.2 R6.1 R9.1 R11.2 U1.3 U1.4 | length 283.3
  TopLayer w0.254: P4.6@36.207,89.408 ccw(c34.703,89.408) 35.766,90.472 ccw(c36.83,91.535) P4.6@36.83,90.031 ; P4.6@36.461,89.408 ccw(c35.57,89.408) 36.2,90.038 ; P4.6 35.687,90.551 35.687,92.456 36.449,93.218 37.211,93.218 37.973,93.98 37.973,98.425 P4.2 ; P4.6@36.83,89.777 cw(c36.83,90.668) 36.2,90.038 ; P4.2@36.83,98.945 cw(c36.83,97.441) 37.894,98.504 cw(c38.957,99.568) P4.2@37.453,99.568 ; P4.2@36.83,99.199 cw(c36.83,98.308) 37.46,98.938 cw(c38.09,99.568) P4.2@37.199,99.568 ; v2@37.785,90.236 ccw(c37.149,89.6) 37.149,90.5 ccw(c37.149,91.401) v2@37.785,90.764 ; v2(38.049,90.5) 36.662,90.5 36.2,90.038 ; R9.1@39.301,101.85 cw(c40.248,101.85) 39.578,102.52 ; R9.1@39.395,101.138 39.395,102.337 40.64,103.581 44.323,103.581 48.336,107.594 57.912,107.594 58.217,107.29 58.217,100.076 58.725,99.568 ; R9.1@39.555,101.85 cw(c41.115,101.85) 40.012,102.953 ; P3.9@59.067,81.788 ccw(c57.563,81.788) 58.626,82.852 ccw(c59.69,83.915) P3.9@59.69,82.411 ; P3.2@59.122,99.311 ccw(c58.725,99.132) 58.725,99.568 ; P3.2@59.122,99.825 cw(c58.725,100.004) 58.725,99.568 ; P3.9@59.321,81.788 ccw(c58.43,81.788) 59.06,82.418 ccw(c59.69,83.048) P3.9@59.69,82.157 ; P3.2@59.321,99.568 cw(c58.43,99.568) 59.06,98.938 cw(c59.69,98.308) P3.2@59.69,99.199 ; P3.9 58.547,82.931 58.547,98.425 P3.2 ; P3.2@59.69,98.945 ccw(c59.69,97.441) 58.626,98.504 ccw(c57.563,99.568) 59.067,99.568 58.725,99.568
  TopLayer w0.4: P1.2 28.956,99.568 P4.2@36.576,99.568 ; 34.311,105.274 ccw(c33.158,106.426) D2.K@34.788,106.426 ; 34.612,105.575 cw(c35.338,104.85) D2.K@35.338,105.876 ; 35.457,100.687 ccw(c36.83,102.059) P4.2@36.83,100.118 ; D2.K 33.528,104.491 33.528,102.616 P4.2@36.576,99.568 ; 36.071,100.073 cw(c35.565,99.568) P4.2@36.28,99.568 ; 36.14,100.004 ccw(c36.83,100.693) P4.2@36.83,99.718 ; P4.2@36.441,99.179 ccw(c35.502,98.24) 35.502,99.568 ccw(c35.502,100.896) P4.2@36.441,99.957 ; P4.2@37.219,99.179 cw(c38.158,98.24) 38.158,99.568 cw(c38.158,100.896) P4.2@37.219,99.957 ; R9.1@38.97,101.138 cw(c38.458,100.626) 39.182,100.626 cw(c39.906,100.626) R9.1@39.394,101.138 ; R9.1 39.182,100.142 38.608,99.568 P4.2 P4.2@36.576,99.568 ; v1@43.888,76.762 ccw(c43.146,77.504) 44.196,77.504 ccw(c45.246,77.504) v1@44.504,76.762 ; R6.1@43.918,78.532 cw(c43.246,77.86) 44.196,77.86 ; R6.1@43.918,79.456 ccw(c43.406,79.968) 44.13,79.968 ccw(c44.854,79.968) R6.1@44.342,79.456 ; U1.4@44.061,87.003 ccw(c43.122,87.942) 44.45,87.942 ccw(c45.778,87.942) U1.4@44.839,87.003 ; U1.3@44.061,88.765 cw(c43.122,87.826) 44.45,87.826 cw(c45.778,87.826) U1.3@44.839,88.765 ; 44.13,84.514 cw(c46.55,84.514) U1.4@44.839,86.225 ; 44.13,85.479 cw(c45.585,85.479) U1.4@44.556,86.508 ; v1(44.196,76.454) 44.196,78.928 R6.1 44.13,86.294 U1.4 U1.3 ; 44.196,78.179 cw(c44.695,78.179) R6.1@44.342,78.532 ; C1.1@49.316,66.45 ccw(c48.804,66.962) 49.528,66.962 ccw(c50.252,66.962) C1.1@49.74,66.45 ; 49.528,74.786 cw(c51.452,74.786) v1@50.092,76.146 ; 49.528,75.751 cw(c50.487,75.751) v1@49.809,76.429 ; v1(49.784,76.454) 49.528,76.198 C1.1 54.667,66.237 59.182,61.722 h3.1 61.722,64.008 61.722,65.024 63.688,66.99 R11.2 64.77,72.898 h1.1 61.976,75.692 61.976,79.502 P3.9 ; C1.1@49.99,66.025 cw(c50.502,65.513) 50.502,66.237 cw(c50.502,66.962) C1.1@49.99,66.45 ; 58.063,62.841 cw(c56.691,61.468) h3.1@58.632,61.468 ; 58.677,62.227 ccw(c59.182,62.733) 59.182,62.018 ccw(c59.182,63.346) 60.121,62.407 ccw(c61.06,61.468) h3.1@59.732,61.468 ; h3.1@58.746,62.158 cw(c58.057,61.468) h3.1@59.032,61.468 ; P3.9@59.69,81.238 cw(c59.69,79.91) 60.629,80.849 cw(c61.568,81.788) P3.9@60.24,81.788 ; P3.2 61.468,101.346 62.992,101.346 63.246,101.092 P2.2 ; P3.2@59.69,100.118 ccw(c59.69,101.446) 60.629,100.507 ccw(c61.568,99.568) P3.2@60.24,99.568 ; h1.1@63.712,73.406 ccw(c62.384,73.406) 63.323,74.345 ccw(c64.262,75.284) h1.1@64.262,73.956 ; h1.1@63.873,73.017 cw(c61.708,70.852) 64.77,70.852 ; h1.1@64.156,73.3 cw(c62.673,71.817) 64.77,71.817 ; R11.2@64.308,66.778 ccw(c63.796,66.266) 63.796,66.99 ccw(c63.796,67.714) R11.2@64.308,67.202 ; h1.1@64.439,73.583 cw(c63.639,72.783) h1.1@64.77,72.783 ; R11.2@64.558,67.202 ccw(c64.046,67.714) 64.77,67.714 ccw(c65.494,67.714) R11.2@64.982,67.202 ; P2.2@65.744,100.526 ccw(c64.379,99.161) 64.379,101.092 ccw(c64.379,103.023) P2.2@65.744,101.658
  BottomLayer w0.254: h2.1@31.361,71.239 31.75,71.239 h2.1@32.139,71.239 ; P4.6@36.83,89.777 ccw(c36.83,90.668) 37.46,90.038 ccw(c38.09,89.408) P4.6@37.199,89.408 ; P4.6@36.83,90.031 ccw(c36.83,91.535) 37.894,90.472 ccw(c38.957,89.408) P4.6@37.453,89.408 ; 37.246,90.098 cw(c37.638,89.418) v2@37.917,90.152 ; 37.354,90.16 ccw(c36.994,90.783) v2@37.689,90.597 ; P4.6@37.469,89.737 cw(c38.153,89.342) v2@38.083,90.129 ; 37.502,90.08 ccw(c37.082,90.5) v2@37.676,90.5 ; 37.64,90.032 ccw(c37.216,90.277) v2@37.689,90.404 ; v2@38.041,90.127 ccw(c38.017,88.999) 37.219,89.797 37.922,90.5 v2(38.049,90.5)
  BottomLayer w0.4: pad.1@25.092,77.658 cw(c24.35,76.915) 25.4,76.915 cw(c26.45,76.915) pad.1@25.708,77.658 ; pad.1 25.4,74.422 28.194,71.628 h2.1 ; h2.1@31.361,71.239 ccw(c30.422,70.3) 30.422,71.628 ccw(c30.422,72.956) h2.1@31.361,72.017 ; 33.078,71.628 34.036,71.628 35.306,72.898 43.434,72.898 44.196,73.66 v1(44.196,76.454) v1(49.784,76.454) ; v1@43.888,76.146 cw(c43.146,75.404) 44.196,75.404 cw(c45.246,75.404) 44.504,76.146 cw(c45.246,75.404) 45.246,76.454 cw(c45.246,77.504) v1@44.504,76.762 ; v1@49.476,76.146 ccw(c48.734,75.404) 48.734,76.454 ccw(c48.734,77.504) v1@49.476,76.762 ; h1.1 65.545,73.406 ; h1.1@64.66,73.027 cw(c65.545,72.185) 65.545,73.406 ; h1.1@64.66,73.785 ccw(c65.545,74.627) 65.545,73.406 ; pad.2@69.669,77.965 cw(c68.619,77.965) 69.361,77.223 cw(c70.104,76.48) pad.2@70.104,77.53 ; pad.2 65.545,73.406
NetD2_A: D2.A R2.1 | length 7.1
  TopLayer w0.4: D2.A 40.894,106.426 41.336,106.868 R2.1 ; D2.A@39.727,106.037 cw(c40.666,105.098) 40.666,106.426 cw(c40.666,107.754) D2.A@39.727,106.815 ; R2.1@42.464,106.656 ccw(c41.952,106.144) 41.952,106.868 ccw(c41.952,107.592) R2.1@42.464,107.08
NetD3_1: D3.1 U1.1 | length 8
  BottomLayer w0.3: U1.1@44.026,94.658 ccw(c43.001,95.683) 44.45,95.683 ccw(c45.899,95.683) U1.1@44.874,94.658 ; U1.1 44.45,97.53 ; D3.1@44.633,98.165 cw(c43.967,98.013) 44.45,97.53 ; D3.1@45.085,97.713 ccw(c44.933,97.047) 44.45,97.53 ; D3.1 44.45,97.53
NetD3_2: D3.2 R5.1 U1.5 | length 25.1
  TopLayer w0.4: R5.1@49.252,83.52 ccw(c48.74,84.032) 49.464,84.032 ccw(c50.188,84.032) R5.1@49.676,83.52 ; R5.1 49.464,85.278 50.8,86.614 ; 51.038,87.778 cw(c49.874,86.614) U1.5@51.52,86.614 ; 51.356,87.46 ccw(c52.07,88.173) U1.5@52.07,87.164 ; U1.5@51.669,86.238 ccw(c50.8,85.423) 50.8,86.614 ; U1.5@51.669,86.99 cw(c50.8,87.805) 50.8,86.614 ; D3.2@52.015,97.839 cw(c51.644,97.276) 52.318,97.276 ; D3.2 52.318,97.276 ; D3.2@52.621,97.839 ccw(c52.992,97.276) 52.318,97.276 ; 50.8,86.614 U1.5 52.07,86.746 50.292,88.524 50.292,95.25 52.318,97.276
Neth3_2: h3.2 R11.1 | length 18.5
  TopLayer w0.254: h3.2@56.642,60.845 cw(c56.642,59.341) 57.706,60.404 cw(c58.769,61.468) h3.2@57.265,61.468 ; h3.2@56.642,61.099 cw(c56.642,60.208) 57.272,60.838 cw(c57.902,61.468) h3.2@57.011,61.468 ; h3.2 58.674,59.436 62.484,59.436 64.77,61.722 R11.1 ; R11.1@64.506,64.826 cw(c63.87,64.19) 64.77,64.19 cw(c65.67,64.19) R11.1@65.034,64.826
NetP5_1: P5.1 R6.2 | length 28.4
  TopLayer w0.4: R6.2@42.018,79.456 ccw(c41.052,80.422) 42.418,80.422 ; R6.2 42.418,79.182 42.418,98.806 P5.1 ; P5.1@45.678,102.616 cw(c44.35,102.616) 45.289,101.677 cw(c46.228,100.738) P5.1@46.228,102.066
NetR4_2: R4.2 R5.2 U1.2 | length 41.3
  TopLayer w0.4: U1.2 44.704,91.44 46.482,91.44 47.564,90.358 ; U1.2@44.556,91.8 ccw(c45.425,92.669) 45.425,91.44 ; U1.2@44.839,91.305 cw(c45.165,90.979) 45.165,91.44 ; U1.2@44.839,92.083 ccw(c46.391,93.635) 46.391,91.44 ; v1@47.19,97.736 cw(c46.289,96.835) 47.564,96.835 ; R5.2@47.352,83.52 ccw(c46.84,84.032) 47.564,84.032 ccw(c48.288,84.032) R5.2@47.776,83.52 ; v1@47.358,97.632 cw(c47.261,97.345) 47.564,97.345 cw(c47.976,97.345) v1@47.743,97.685 ; v1(47.498,98.044) 47.498,97.414 47.564,97.348 47.564,90.358 ; R5.2 47.564,90.358 ; 47.564,97.153 cw(c48.389,97.153) v1@47.806,97.736 ; v1@50.238,98.352 ccw(c48.883,99.707) 50.8,99.707 ; v1@50.521,98.069 ccw(c49.848,98.742) 50.8,98.742 ; v1(50.546,98.044) 50.8,98.298 50.8,99.822 51.562,100.584 52.578,100.584 53.274,101.28 R4.2 ; R4.2@53.062,102.154 cw(c52.55,101.642) 53.274,101.642 cw(c53.998,101.642) R4.2@53.486,102.154
  BottomLayer w0.4: v1(47.498,98.044) v1(50.546,98.044) ; v1@47.806,97.736 cw(c48.548,96.994) 48.548,98.044 cw(c48.548,99.094) v1@47.806,98.352 ; v1@50.238,97.736 ccw(c49.496,96.994) 49.496,98.044 ccw(c49.496,99.094) v1@50.238,98.352
RST: C1.2 h3.7 P4.3 R1.1 | length 80.1
  TopLayer w0.254: 33.782,90.678 34.036,90.678
  TopLayer w0.4: v1@33.274,61.541 cw(c33.274,60.491) 34.017,61.233 cw(c34.759,61.976) v1@33.709,61.976 ; v1(33.274,61.976) 35.56,59.69 42.164,59.69 h3.7 ; v1@33.474,66.094 ccw(c32.732,66.836) 33.782,66.836 ccw(c34.832,66.836) v1@34.09,66.094 ; v1(33.782,65.786) 33.782,90.678 ; 34.036,90.678 33.782,90.932 33.782,94.996 35.814,97.028 ; P4.3@36.369,96.727 ccw(c35.814,96.365) 35.814,97.028 ; P4.3@36.369,97.329 cw(c35.814,97.691) 35.814,97.028 ; P4.3 35.814,97.028 ; h3.7@43.392,61.468 cw(c42.064,61.468) 43.003,60.529 cw(c43.942,59.59) 43.942,60.918 cw(c43.942,59.59) 44.881,60.529 cw(c45.82,61.468) h3.7@44.492,61.468 ; h3.7@43.553,61.857 ccw(c42.614,62.796) 43.942,62.796 ccw(c45.27,62.796) h3.7@44.331,61.857 ; R1.1 43.942,64.067 h3.7 ; R1.1@43.728,64.106 cw(c43.211,63.59) 43.942,63.59 ; 43.942,63.599 cw(c44.66,63.599) R1.1@44.152,64.106 ; 48.458,63.698 cw(c49.278,62.877) C1.2@49.278,64.037 ; C1.2 49.097,64.337 47.752,62.992 47.752,60.706 47.244,60.198 45.212,60.198 h3.7
  BottomLayer w0.4: v1@32.966,62.284 ccw(c32.224,63.026) 33.274,63.026 ccw(c34.324,63.026) v1@33.582,62.284 ; v1(33.274,61.976) 33.274,65.278 v1(33.782,65.786) ; 33.274,63.509 cw(c36.059,63.509) v1@34.09,65.478 ; 33.274,64.475 cw(c35.093,64.475) v1@33.807,65.761
RX: h1.7 P3.4 | length 12.7
  TopLayer w0.4: P3.4@59.69,93.938 cw(c59.69,92.61) 60.629,93.549 cw(c61.568,94.488) P3.4@60.24,94.488 ; P3.4 61.468,92.71 61.468,91.694 64.262,88.9 h1.7 ; 63.143,90.019 cw(c61.771,88.646) h1.7@63.712,88.646 ; 63.757,89.405 ccw(c64.262,89.911) h1.7@64.262,89.196 ; 63.826,89.336 cw(c63.137,88.646) h1.7@64.112,88.646
SD1: h2.4 P4.10 | length 9.3
  BottomLayer w0.4: h2.4 P4.10 ; h2.4@32.139,78.859 cw(c33.078,77.92) 33.078,79.248 cw(c33.078,80.576) h2.4@32.139,79.637 ; P4.10@36.441,78.859 ccw(c35.502,77.92) 35.502,79.248 ccw(c35.502,80.576) P4.10@36.441,79.637
SD2: h2.3 P4.11 | length 9.3
  BottomLayer w0.4: h2.3 P4.11 ; h2.3@32.139,76.319 cw(c33.078,75.38) 33.078,76.708 cw(c33.078,78.036) h2.3@32.139,77.097 ; P4.11@36.441,76.319 ccw(c35.502,75.38) 35.502,76.708 ccw(c35.502,78.036) P4.11@36.441,77.097
SD3: h2.2 P4.12 | length 9.3
  BottomLayer w0.4: h2.2 P4.12 ; h2.2@32.139,73.779 cw(c33.078,72.84) 33.078,74.168 cw(c33.078,75.496) h2.2@32.139,74.557 ; P4.12@36.441,73.779 ccw(c35.502,72.84) 35.502,74.168 ccw(c35.502,75.496) P4.12@36.441,74.557
SDD: h2.6 P4.8 | length 9.3
  BottomLayer w0.4: h2.6 P4.8 ; h2.6@32.139,83.939 cw(c33.078,83) 33.078,84.328 cw(c33.078,85.656) h2.6@32.139,84.717 ; P4.8@36.441,83.939 ccw(c35.502,83) 35.502,84.328 ccw(c35.502,85.656) P4.8@36.441,84.717
TX: h1.8 P3.3 | length 11.9
  TopLayer w0.4: P3.3@59.69,96.478 cw(c59.69,95.15) 60.629,96.089 cw(c61.568,97.028) P3.3@60.24,97.028 ; P3.3 62.484,94.234 62.484,92.964 h1.8 ; h1.8@63.712,91.186 ccw(c62.384,91.186) 63.323,92.125 ccw(c64.262,93.064) h1.8@64.262,91.736
VIN: P4.1 R7.1 | length 66.1
  TopLayer w0.3: v1@38.519,70.701 ccw(c37.078,72.142) 39.116,72.142 ; v1@38.731,70.489 ccw(c37.802,71.418) 39.116,71.418 ; v1(38.862,70.358) 39.116,70.612 39.116,73.66 40.132,74.676 40.132,97.028 ; v1@39.281,97.193 cw(c37.227,95.139) 40.132,95.139 ; v1@39.493,97.405 cw(c37.951,95.863) 40.132,95.863 ; v1(39.624,97.536) 40.132,97.028 ; v1@39.705,97.617 cw(c38.675,96.587) 40.132,96.587 ; v1@39.814,97.09 cw(c39.927,96.823) 40.132,97.028 ; R7.1 40.64,66.99 ; v1@40.07,97.346 ccw(c40.337,97.233) 40.132,97.028 ; v1@40.403,67.395 cw(c40.176,66.99) 40.64,66.99 ; R7.1@40.465,66.322 cw(c41.123,66.507) 40.64,66.99 ; v1(40.64,67.818) 40.64,66.99 ; v1@40.877,67.395 ccw(c41.104,66.99) 40.64,66.99
  BottomLayer w0.254: v1@38.603,69.921 cw(c38.333,69.466) 38.862,69.466 cw(c39.391,69.466) v1@39.121,69.921 ; v1@38.862,69.873 38.862,69.466 39.116,69.212 39.759,69.212
  BottomLayer w0.3: P4.1@36.83,101.508 cw(c36.83,100.059) 37.854,101.084 cw(c38.879,102.108) P4.1@37.43,102.108 ; P4.1 39.624,99.314 v1(39.624,97.536) ; v1@38.765,69.883 cw(c38.452,68.347) 39.759,69.212 ; v1@38.825,70.177 cw(c38.657,69.351) 39.36,69.816 ; v1@38.862,69.873 cw(c38.862,68.702) 39.69,69.53 cw(c40.518,70.358) v1@39.347,70.358 ; v1(38.862,70.358) 40.64,68.58 ; v1@39.273,69.947 cw(c37.144,67.818) v1@40.155,67.818 ; v1@39.281,97.879 ccw(c38.453,98.707) 39.624,98.707 ccw(c40.795,98.707) v1@39.967,97.879 ; v1@39.337,70.261 ccw(c40.096,70.107) 39.45,69.679 ; 39.785,69.435 cw(c38.169,67.818) v1@40.455,67.818 ; 40.297,68.923 cw(c39.193,67.818) v1@40.755,67.818 ; v1@40.435,68.257 ccw(c40.284,68.58) 40.64,68.58 ; v1(40.64,67.818) 40.64,68.58 ; v1@40.845,68.257 cw(c40.996,68.58) 40.64,68.58
pads on no net: P1.3 P2.3 P4.13 P4.14

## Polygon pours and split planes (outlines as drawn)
GND on TopLayer "TopLayer-GND" (solid, pour order 8): 21.59,107.95 21.844,108.204 73.406,108.204 73.406,59.182 73.66,58.928 21.59,58.928 21.59,108.204
GND on BottomLayer "BOTT-GND" (solid, pour order 7): 21.59,107.95 21.844,108.204 73.406,108.204 73.406,59.182 73.66,58.928 21.59,58.928 21.59,108.204

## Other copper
TopLayer:
  text ".GTL" at 178.791,130.48 h2.29
BottomLayer:
  text "P/N XXXXXX-XXX REV A" at 59.944,131.75 h1.91
  text ".GBL" at 178.791,130.48 h2.29

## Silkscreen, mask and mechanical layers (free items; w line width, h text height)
TopOverlay:
  circle w0.254: c25.4,77.902 r2.857
  circle w0.254: c70.104,77.902 r2.857
  rectangle: 33.553,136.906 52.603,141.986
  rectangle: 33.553,144.272 52.603,149.352
  lines w0.254: 61.788,146.887 ccw(c63.017,147.892) 61.791,146.884
  text "C" at 64.414,146.939 h1.52
  text "2002 COMPANY NAME" at 68.224,146.939 h1.91
  text "S/N" at 27.203,145.732 h1.91
  text "BOARD NAME" at 64.414,142.494 h1.91
  text "ASSY NO.: XXXXXX" at 64.414,138.684 h1.91
  text "REV" at 27.203,138.176 h1.91
  text ".GTO" at 178.791,130.48 h2.29
  text "P1" at 171.789,76.048 h1.52
  text "REV5" at 70.866,66.294 h2.03 r90
  text "ESD" at 24.892,65.278 h2.03 r90
  text "02122019" at 72.898,59.944 h1 r90
BottomOverlay:
  text "USB" at 45.974,104.648 h3
  text "ANTENNA" at 37.338,67.818 h3
TopPaste:
  text ".GTP" at 178.791,130.48 h2.29
BottomPaste:
  text ".GBP" at 253.975,256.21 h2.29
TopSolder:
  text ".GTS" at 178.791,130.48 h2.29
BottomSolder:
  text ".GBS" at 253.975,256.21 h2.29
Mechanical1:
  lines w0.508: 20.574,58.42 74.168,58.42 74.168,108.712 20.828,108.712 20.828,58.674
Mechanical4:
  text ".Pcb_File_Name_No_Path" at 130.531,135.306 h2.29
  text ".Printout_Name" at 130.531,130.48 h2.29
DrillDrawing:
  text ".LEGEND" at 199.517,31.471 h2.29
  text "Drilling Details." at 199.517,27.661 h2.29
